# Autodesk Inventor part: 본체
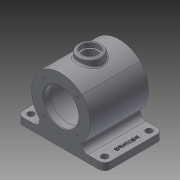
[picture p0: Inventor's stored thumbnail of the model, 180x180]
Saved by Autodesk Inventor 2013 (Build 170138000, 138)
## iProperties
Company: 한국ATC센터
Created: 2014-08
Part Number: 본체
Document SubType Name: Modeling
Designer: KYOUNG IL JANG
Density: 1 g/cm^3
Material: 일반
Mass: 1211.76 g
Surface Area: 1019.41 cm^2
Volume: 447.145 cm^3
Author: KYOUNG IL JANG
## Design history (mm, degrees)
sketch "스케치1"
  geometry: L1 (-50, 0)-(50, 0); L2 (-36.062, 36.062)-(36.062, 36.062); L3 (36.062, 36.062)-(36.062, -36.062); L4 (36.062, -36.062)-(-36.062, -36.062); L5 (-36.062, -36.062)-(-36.062, 36.062); A1 r 53.623 centre (-3.623, 0) between (36.062, -36.062) and (36.062, 36.062); A2 r 53.623 centre (3.623, 0) between (-36.062, 36.062) and (-36.062, -36.062); A3 r 53.623 centre (0, -3.623) between (36.062, 36.062) and (-36.062, 36.062); A4 r 53.623 centre (0, 3.623) between (-36.062, -36.062) and (36.062, -36.062); 4 further points
  constraints: 11 point on circle, 10 end point, 5 coincident, 4 centre point, 4 horizontal alignment, 3 equal radius, 2 horizontal, 2 parallel, 2 perpendicular, 1 midpoint
  dimensions: "d83" = 51 distance of L2.end point (0, 0); "d84" = 100 distance of L1.end L1.start
extrude "돌출1" new body sketch "스케치1" stored distance "d9" = 100; taper "d10" = 0 deg
node "작업 평면1"
sketch "스케치2"
  geometry: L1 (75, 50)-(-75, 50); L2 (-75, 50)-(-75, -50); L3 (-75, -50)-(75, -50); L4 (75, -50)-(75, 50); 4 further points
  constraints: 8 end point, 3 midpoint, 2 parallel, 2 vertical alignment, 1 horizontal, 1 horizontal alignment, 1 perpendicular
  dimensions: "d14" = 150 distance of L2.end L3.end; "d82" = 100 distance of L1.end L2.end
extrude "돌출2" join sketch "스케치2" distance "d15" = 12; taper "d16" = 0 deg
node "작업 평면3"
  node "작업 평면4"
sketch "스케치3"
  geometry: C1 r 20 at (0, 0); 1 further point
  constraints: 2 coincident, 1 centre point
  dimensions: "d19" = 40 diameter of C1
extrude "돌출3" join sketch "스케치3" stored distance "d23" = 12; taper "d24" = 0 deg
node "작업 평면6"
  node "작업 평면5"
sketch "스케치4"
  geometry: C1 r 37.5 at (0, 0); 1 further point
  constraints: 1 centre point, 1 coincident
  dimensions: "d25" = 75 diameter of C1
extrude "돌출4" cut sketch "스케치4" stored distance "d26" = 76; taper "d27" = 0 deg
sketch "스케치5"
  geometry: C1 r 30 at (0, 0); 1 further point
  constraints: 1 centre point, 1 coincident
  dimensions: "d28" = 60 diameter of C1
extrude "돌출5" cut sketch "스케치5" stored distance "d29" = 116; taper "d30" = 0 deg
hole "구멍1" diameter "d33" = 25; stored, may be unused: countersink angle "d37" = 90 deg, drill point angle "d39" = 0 deg; dims "d31" = 10, "d32" = 10, "d34" = 6, "d35" = 30, "d36" = 8, "d38" = 40
sketch "스케치6"
  geometry: L1 (-75, -50)-(-75, 50) reference; L2 (-75, 50)-(75, 50) reference; L3 (75, -50)-(-75, -50) reference; L4 (75, 50)-(75, -50) reference; L5 (0, -50)-(0, 50); L6 (-75, 0)-(75, 0); L7 (-63, -38)-(63, 38); C1 r 5.5 at (-63, -38); C2 r 5.5 at (-63, 38); C3 r 5.5 at (63, -38); C4 r 5.5 at (63, 38); 2 further points
  constraints: 6 end point, 6 midpoint, 4 centre point, 2 equal radius, 2 horizontal alignment, 2 vertical alignment
  dimensions: "d49" = 11 diameter of C1; "d50" = 11 diameter of C2; "d100" = 12 distance from line of L2 C2.centre; "d101" = 12 distance from line of C2.centre L1
extrude "돌출6" cut sketch "스케치6" distance "d53" = 116; taper "d54" = 0 deg
sketch "스케치8"
  geometry: L1 (75, 50)-(75, -50) reference; 2 further points
  constraints: 1 horizontal alignment, 1 other
  dimensions: "d55" = 12 distance from line of L1 point (63, 0)
feature "엠보싱1" sketch "스케치8" dims "d57" = 1, "d58" = 0, "d83" = 51, "d84" = 100
fillet "모깎기2" dims "d60" = 10
fillet "모깎기5" dims "d63" = 10
fillet "모깎기7" dims "d65" = 3
sketch "스케치9"
  geometry: L1 (0, 0)-(-28.284, 28.284); L2 (0, 0)-(0, 40); C1 r 30 at (0, 0) reference; A1 r 40 centre (0, 0) between (-28.284, 28.284) and (0, 40); 1 further point
  constraints: 4 end point, 2 coincident, 2 point on circle, 1 centre point, 1 vertical
  dimensions: "d66" = 80 diameter of A1; "d67" = 45 deg angle of L1 L2
hole "M4" sketch "스케치9" at (-28.284, 28.284) diameter "d68" = 3.242; stored, may be unused: countersink angle "d72" = 90 deg, drill point angle "d74" = 118 deg; dims "d69" = 8, "d70" = 30, "d71" = 8, "d73" = 10
fillet "모깎기8" dims "d78" = 3
chamfer "모따기1" distance "d79" = 1; stored, may be unused: second distance "d80" = 2, angle "d81" = 45 deg
node "솔리드1"
pattern_circular "원형 패턴1" dims angle "d76" = 360 deg
mirror "대칭1"
